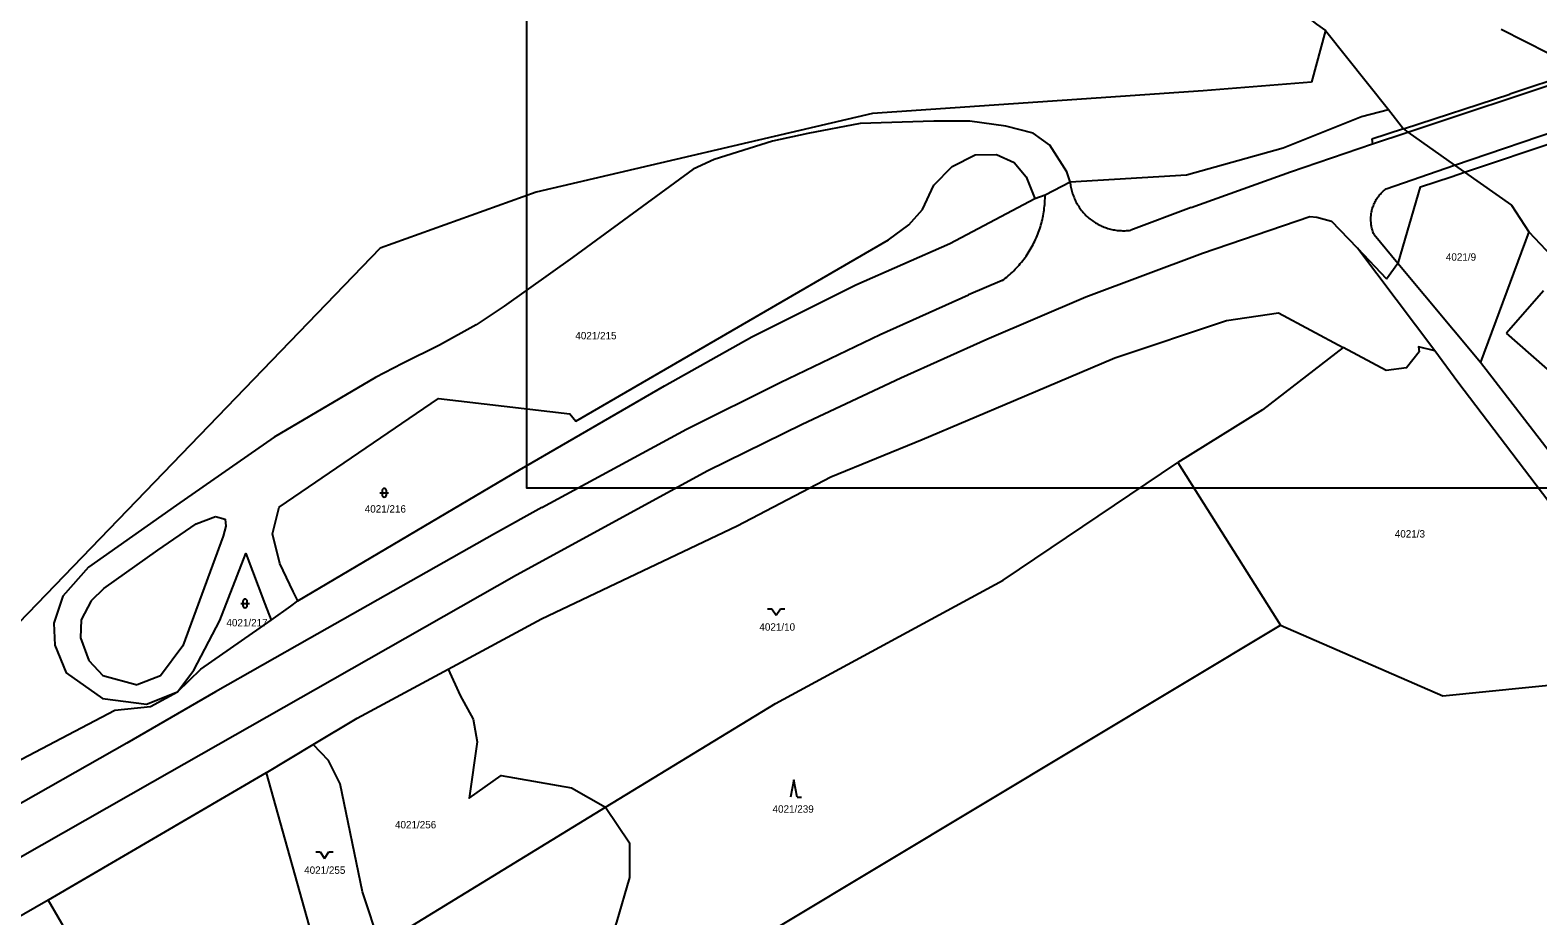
# Model space of a CAD drawing. Extents: x -869103 to -863415, y -1015889 to -1012477.
# Drawn here: x -867614.3 to -867267.3, y -1013598.4 to -1013394.6 of the extents above; entities that cross this region are included whole.
import ezdxf

# ---------------------------------------------------------------- set-up
doc = ezdxf.new("R2010")
doc.units = 0
for name, color, linetype in [('Hranice katastralního území', 7, 'Continuous'), ('Hranice parcel', 7, 'Continuous'), ('ML1000', 7, 'Continuous'), ('Parcelní čísla', 7, 'Continuous'), ('Vnitřní kresba', 7, 'Continuous'), ('Značky kultur', 7, 'Continuous')]:
    doc.layers.add(name, color=color, linetype=linetype)

msp = doc.modelspace()

# ---------------------------------------------------------------- linework, layer by layer
at = {"layer": 'Hranice katastralního území'}
msp.add_line((-867316.19, -1013394.74), (-867319.36, -1013406.56), dxfattribs=at)
for points in [[(-867342.67, -1013374.58), (-867330.42, -1013383.91), (-867327.52, -1013386.12), (-867321.46, -1013390.73), (-867318.19, -1013393.22), (-867316.19, -1013394.74)], [(-867319.36, -1013406.56), (-867344.3, -1013408.59), (-867420.44, -1013413.79), (-867497.84, -1013431.94), (-867533.79, -1013444.77), (-867635.74, -1013550.41), (-867753.76, -1013618.81)]]:
    msp.add_lwpolyline(points, dxfattribs=at)
at = {"layer": 'Hranice parcel'}
for p, q in [((-867316.19, -1013394.74), (-867319.36, -1013406.56)), ((-867316.19, -1013394.74), (-867301.67, -1013412.9)), ((-867257.25, -1013403.84), (-867275.71, -1013394.51)), ((-867307.87, -1013414.51), (-867301.67, -1013412.9)), ((-867269.34, -1013441), (-867280.47, -1013471.01)), ((-867302.08, -1013451.88), (-867299.47, -1013448.24)), ((-867299.47, -1013448.24), (-867299.32, -1013448.02)), ((-867299.47, -1013448.24), (-867280.47, -1013471.01)), ((-867326.96, -1013459.67), (-867312.12, -1013467.62)), ((-867285.68, -1013475.65), (-867290.97, -1013468.44)), ((-867250.1, -1013522.49), (-867285.68, -1013475.65)), ((-867350.14, -1013494.15), (-867326.55, -1013531.51)), ((-867326.55, -1013531.51), (-867289.11, -1013547.84)), ((-867560.01, -1013565.49), (-867549.22, -1013559.03)), ((-867560.01, -1013565.49), (-867610.16, -1013594.81)), ((-867560.01, -1013565.49), (-867546.67, -1013613.13)), ((-867489.72, -1013568.95), (-867481.86, -1013573.46)), ((-867533.74, -1013605.21), (-867481.86, -1013573.46)), ((-867481.86, -1013573.46), (-867476.41, -1013581.67)), ((-867533.74, -1013605.21), (-867537.85, -1013592.91)), ((-867610.16, -1013594.81), (-867618.83, -1013599.8)), ((-867610.16, -1013594.81), (-867585.92, -1013636.93))]:
    msp.add_line(p, q, dxfattribs=at)
for points in [[(-867342.67, -1013374.58), (-867330.42, -1013383.91), (-867327.52, -1013386.12), (-867321.46, -1013390.73), (-867318.19, -1013393.22), (-867316.19, -1013394.74)], [(-867319.36, -1013406.56), (-867344.3, -1013408.59), (-867420.44, -1013413.79), (-867497.84, -1013431.94), (-867533.79, -1013444.77), (-867635.74, -1013550.41), (-867753.76, -1013618.81)], [(-867301.67, -1013412.9), (-867298.21, -1013417.34), (-867297.17, -1013418.08), (-867286.44, -1013425.71), (-867284.15, -1013427.34)], [(-867374.93, -1013429.52), (-867375.68, -1013427.21), (-867379.62, -1013421.07), (-867383.48, -1013418.35), (-867389.72, -1013416.68), (-867398.04, -1013415.57), (-867406.32, -1013415.6), (-867423.28, -1013416.13), (-867435.3, -1013418.44), (-867443.46, -1013420.18), (-867456.89, -1013424.42), (-867461.74, -1013426.63), (-867489.48, -1013446.92), (-867505.2, -1013458.13), (-867511.7, -1013462.41), (-867520.1, -1013467.13), (-867528.6, -1013471.3), (-867534.88, -1013474.58), (-867558.14, -1013488.32), (-867580.62, -1013503.94), (-867600.88, -1013518.22), (-867606.83, -1013524.84), (-867608.91, -1013531.09), (-867608.65, -1013536.16), (-867606.03, -1013542.52), (-867597.67, -1013548.45), (-867587.53, -1013549.72), (-867580.45, -1013546.87)], [(-867374.93, -1013429.52), (-867348.14, -1013427.94), (-867325.89, -1013421.67), (-867307.87, -1013414.51)], [(-867552.75, -1013525.96), (-867553.8, -1013523.79), (-867556.9, -1013517.37), (-867558.56, -1013510.51), (-867557.02, -1013504.41), (-867520.32, -1013479.37), (-867490.1, -1013482.92), (-867488.74, -1013484.61), (-867416.74, -1013442.85), (-867412.04, -1013439.42), (-867408.89, -1013435.91), (-867406.29, -1013430.33), (-867402.13, -1013426.03), (-867396.77, -1013423.29), (-867391.86, -1013423.26), (-867387.8, -1013425.1), (-867385.03, -1013428.34), (-867383.05, -1013433.35)], [(-867299.32, -1013448.02), (-867294.3, -1013430.7), (-867287.22, -1013428.37), (-867284.15, -1013427.34)], [(-867284.15, -1013427.34), (-867273.32, -1013434.93), (-867269.34, -1013441)], [(-867383.05, -1013433.35), (-867380.7, -1013432.51), (-867374.93, -1013429.52)], [(-867552.75, -1013525.96), (-867501.66, -1013495.78), (-867468.31, -1013476.49), (-867448.21, -1013465.21), (-867424.27, -1013453.24), (-867402.6, -1013443.75), (-867383.05, -1013433.35)], [(-867269.34, -1013441), (-867241.95, -1013470), (-867213.99, -1013523.37)], [(-867290.97, -1013468.44), (-867308.82, -1013444.81), (-867302.08, -1013451.88)], [(-867518.15, -1013541.67), (-867496.64, -1013530.06), (-867451.58, -1013508.71), (-867430.05, -1013497.43), (-867409, -1013488.8), (-867388.01, -1013479.91), (-867364.62, -1013470.03), (-867338.93, -1013461.42), (-867326.96, -1013459.67)], [(-867312.12, -1013467.62), (-867330.63, -1013481.99), (-867350.14, -1013494.15)], [(-867294.58, -1013468.65), (-867297.48, -1013472.35), (-867302.16, -1013472.96), (-867312.12, -1013467.62)], [(-867290.97, -1013468.44), (-867294.74, -1013467.46), (-867294.58, -1013468.65)], [(-867280.47, -1013471.01), (-867241.81, -1013521.12), (-867224.29, -1013529.55), (-867213.99, -1013523.37)], [(-867481.86, -1013573.46), (-867442.79, -1013549.54), (-867390.35, -1013521.2), (-867350.14, -1013494.15)], [(-867580.45, -1013546.87), (-867576.67, -1013541.9), (-867570.67, -1013530.46), (-867564.73, -1013515.06), (-867560.29, -1013526.62), (-867558.85, -1013530.36)], [(-867558.85, -1013530.36), (-867554.31, -1013527.2), (-867552.75, -1013525.96)], [(-867580.45, -1013546.87), (-867575.05, -1013541.64), (-867558.85, -1013530.36)], [(-867488.53, -1013628.82), (-867464.48, -1013614.37), (-867326.55, -1013531.51)], [(-867289.11, -1013547.84), (-867248.82, -1013543.72), (-867230.89, -1013533.36)], [(-867549.22, -1013559.03), (-867539.05, -1013552.94), (-867518.15, -1013541.67)], [(-867518.15, -1013541.67), (-867515.32, -1013547.76), (-867512.35, -1013553.18), (-867511.46, -1013558.41), (-867513.3, -1013571.37), (-867505.89, -1013566.17), (-867489.72, -1013568.95)], [(-868123.92, -1013837.14), (-868079.76, -1013818.89), (-868033.21, -1013797.81), (-868012.01, -1013785.48), (-867950.07, -1013750.76), (-867862.98, -1013701.19), (-867776.75, -1013651.7), (-867688.32, -1013600.14), (-867594.86, -1013551.1), (-867586.66, -1013550.23), (-867580.45, -1013546.87)], [(-867537.85, -1013592.91), (-867542.99, -1013568.04), (-867545.69, -1013562.72), (-867549.22, -1013559.03)], [(-867476.41, -1013581.67), (-867476.41, -1013589.6), (-867479.36, -1013599.92), (-867488.53, -1013628.82)]]:
    msp.add_lwpolyline(points, dxfattribs=at)
at = {"layer": 'ML1000'}
msp.add_lwpolyline([(-867500, -1013000), (-866875, -1013000), (-866875, -1013500), (-867500, -1013500)], close=True, dxfattribs=at)
at = {"layer": 'Vnitřní kresba'}
for p, q in [((-867297.17, -1013418.08), (-867256.15, -1013404.4)), ((-867257.25, -1013403.84), (-867273.74, -1013409.37)), ((-867298.21, -1013417.34), (-867273.74, -1013409.37)), ((-867286.44, -1013425.71), (-867250.59, -1013413.43)), ((-867298.21, -1013417.34), (-867305.46, -1013419.71)), ((-867324.19, -1013427.23), (-867305.37, -1013420.81)), ((-867305.46, -1013419.71), (-867305.37, -1013420.81)), ((-867305.37, -1013420.81), (-867297.17, -1013418.08)), ((-867284.15, -1013427.34), (-867262.14, -1013419.95)), ((-867347.08, -1013435.42), (-867324.19, -1013427.23)), ((-867302.19, -1013431.11), (-867286.44, -1013425.71)), ((-867347.08, -1013435.42), (-867361, -1013440.66)), ((-867344.49, -1013445.94), (-867319.77, -1013437.5)), ((-867319.77, -1013437.5), (-867318.13, -1013437.66)), ((-867318.13, -1013437.66), (-867314.75, -1013438.6)), ((-867308.82, -1013444.81), (-867314.75, -1013438.6)), ((-867304.97, -1013441.65), (-867299.47, -1013448.24)), ((-867371.31, -1013455.97), (-867344.49, -1013445.94)), ((-867390.57, -1013452.27), (-867398.35, -1013455.55)), ((-867418.69, -1013464.63), (-867398.35, -1013455.55)), ((-867265.94, -1013454.62), (-867274.51, -1013464.37)), ((-867394.09, -1013465.77), (-867371.31, -1013455.97)), ((-867441.69, -1013475.72), (-867418.69, -1013464.63)), ((-867413.93, -1013474.66), (-867394.09, -1013465.77)), ((-867252.22, -1013483.99), (-867274.51, -1013464.37)), ((-867463.22, -1013486.46), (-867441.69, -1013475.72)), ((-867436.66, -1013485.3), (-867413.93, -1013474.66)), ((-867496.57, -1013504.45), (-867463.22, -1013486.46)), ((-867458.31, -1013495.92), (-867436.66, -1013485.3)), ((-867502.38, -1013519.99), (-867458.31, -1013495.92)), ((-867576.16, -1013508.25), (-867571.65, -1013506.55)), ((-867571.65, -1013506.55), (-867569.43, -1013507.12)), ((-867569.43, -1013507.12), (-867569.3, -1013508.79)), ((-867496.57, -1013504.45), (-867507.42, -1013510.56)), ((-867584.92, -1013514.29), (-867576.16, -1013508.25)), ((-867569.89, -1013511.06), (-867579.19, -1013536.34)), ((-867569.3, -1013508.79), (-867569.89, -1013511.06)), ((-867507.42, -1013510.56), (-867550.01, -1013534.61)), ((-867597.39, -1013523.11), (-867584.92, -1013514.29)), ((-867544.77, -1013544.07), (-867502.38, -1013519.99)), ((-867597.39, -1013523.11), (-867600.3, -1013525.94)), ((-867600.3, -1013525.94), (-867602.56, -1013530.31)), ((-867602.56, -1013530.31), (-867602.75, -1013534.49)), ((-867602.75, -1013534.49), (-867600.87, -1013539.7)), ((-867550.01, -1013534.61), (-867571.68, -1013546.91)), ((-867579.19, -1013536.34), (-867584.37, -1013543.17)), ((-867600.87, -1013539.7), (-867597.58, -1013543.16)), ((-867597.58, -1013543.16), (-867589.67, -1013545.25)), ((-867584.37, -1013543.17), (-867589.67, -1013545.25)), ((-867586.17, -1013567.6), (-867544.77, -1013544.07)), ((-867571.68, -1013546.91), (-867592.1, -1013558.73)), ((-867592.1, -1013558.73), (-867683.6, -1013610.49)), ((-867677.53, -1013619.45), (-867586.17, -1013567.6))]:
    msp.add_line(p, q, dxfattribs=at)
for points in [[(-867374.93, -1013429.52), (-867374.9, -1013429.83), (-867374.86, -1013430.14), (-867374.82, -1013430.45), (-867374.76, -1013430.76), (-867374.7, -1013431.06), (-867374.63, -1013431.36), (-867374.55, -1013431.67), (-867374.47, -1013431.97), (-867374.38, -1013432.26), (-867374.28, -1013432.56), (-867374.17, -1013432.85), (-867374.05, -1013433.14), (-867373.93, -1013433.43), (-867373.8, -1013433.71), (-867373.67, -1013433.99), (-867373.52, -1013434.27), (-867373.37, -1013434.54), (-867373.21, -1013434.81), (-867373.05, -1013435.08), (-867372.88, -1013435.34), (-867372.7, -1013435.59), (-867372.52, -1013435.85), (-867372.33, -1013436.09), (-867372.13, -1013436.34), (-867371.93, -1013436.57), (-867371.72, -1013436.81), (-867371.51, -1013437.03), (-867371.29, -1013437.25), (-867371.06, -1013437.47), (-867370.83, -1013437.68), (-867370.6, -1013437.88), (-867370.36, -1013438.08), (-867370.11, -1013438.27), (-867369.86, -1013438.46), (-867369.6, -1013438.64), (-867369.34, -1013438.81), (-867369.08, -1013438.97), (-867368.81, -1013439.13), (-867368.54, -1013439.29), (-867368.26, -1013439.43), (-867367.98, -1013439.57), (-867367.7, -1013439.7), (-867367.42, -1013439.82), (-867367.13, -1013439.94), (-867366.83, -1013440.05), (-867366.54, -1013440.15), (-867366.24, -1013440.24), (-867365.94, -1013440.33), (-867365.64, -1013440.41), (-867365.34, -1013440.48), (-867365.03, -1013440.55), (-867364.73, -1013440.6), (-867364.42, -1013440.65), (-867364.11, -1013440.69), (-867363.8, -1013440.72), (-867363.49, -1013440.75), (-867363.18, -1013440.76), (-867362.86, -1013440.77), (-867362.55, -1013440.77), (-867362.24, -1013440.77), (-867361.93, -1013440.75), (-867361.62, -1013440.73), (-867361.31, -1013440.7), (-867361, -1013440.66)], [(-867304.97, -1013441.65), (-867305.07, -1013441.41), (-867305.17, -1013441.17), (-867305.25, -1013440.92), (-867305.33, -1013440.67), (-867305.41, -1013440.42), (-867305.47, -1013440.17), (-867305.53, -1013439.91), (-867305.58, -1013439.65), (-867305.62, -1013439.4), (-867305.65, -1013439.14), (-867305.68, -1013438.88), (-867305.7, -1013438.61), (-867305.71, -1013438.35), (-867305.71, -1013438.09), (-867305.71, -1013437.83), (-867305.7, -1013437.57), (-867305.68, -1013437.31), (-867305.65, -1013437.05), (-867305.61, -1013436.79), (-867305.57, -1013436.53), (-867305.52, -1013436.28), (-867305.46, -1013436.02), (-867305.39, -1013435.77), (-867305.32, -1013435.52), (-867305.23, -1013435.27), (-867305.14, -1013435.02), (-867305.05, -1013434.78), (-867304.94, -1013434.54), (-867304.83, -1013434.3), (-867304.72, -1013434.07), (-867304.59, -1013433.84), (-867304.46, -1013433.61), (-867304.32, -1013433.39), (-867304.18, -1013433.17), (-867304.03, -1013432.96), (-867303.87, -1013432.75), (-867303.7, -1013432.55), (-867303.53, -1013432.35), (-867303.36, -1013432.16), (-867303.18, -1013431.97), (-867302.99, -1013431.78), (-867302.8, -1013431.61), (-867302.6, -1013431.44), (-867302.4, -1013431.27), (-867302.19, -1013431.11)], [(-867390.57, -1013452.27), (-867390.22, -1013452), (-867389.87, -1013451.73), (-867389.53, -1013451.45), (-867389.19, -1013451.17), (-867388.86, -1013450.88), (-867388.54, -1013450.58), (-867388.21, -1013450.28), (-867387.9, -1013449.97), (-867387.59, -1013449.66), (-867387.29, -1013449.34), (-867386.99, -1013449.01), (-867386.7, -1013448.68), (-867386.41, -1013448.35), (-867386.13, -1013448.01), (-867385.86, -1013447.66), (-867385.59, -1013447.31), (-867385.33, -1013446.96), (-867385.07, -1013446.6), (-867384.82, -1013446.23), (-867384.58, -1013445.87), (-867384.35, -1013445.49), (-867384.12, -1013445.12), (-867383.9, -1013444.73), (-867383.68, -1013444.35), (-867383.48, -1013443.96), (-867383.28, -1013443.57), (-867383.08, -1013443.17), (-867382.9, -1013442.77), (-867382.72, -1013442.37), (-867382.55, -1013441.96), (-867382.38, -1013441.56), (-867382.22, -1013441.14), (-867382.07, -1013440.73), (-867381.93, -1013440.31), (-867381.8, -1013439.89), (-867381.67, -1013439.47), (-867381.55, -1013439.05), (-867381.44, -1013438.62), (-867381.34, -1013438.19), (-867381.24, -1013437.76), (-867381.15, -1013437.33), (-867381.07, -1013436.9), (-867381, -1013436.46), (-867380.93, -1013436.03), (-867380.88, -1013435.59), (-867380.83, -1013435.15), (-867380.79, -1013434.71), (-867380.75, -1013434.27), (-867380.73, -1013433.83), (-867380.71, -1013433.39), (-867380.7, -1013432.95), (-867380.7, -1013432.51)]]:
    msp.add_lwpolyline(points, dxfattribs=at)
at = {"layer": 'Značky kultur'}
for p, q in [((-867533.33, -1013500.59), (-867533.33, -1013501.59)), ((-867532.33, -1013501.59), (-867532.33, -1013500.59)), ((-867533.83, -1013501.09), (-867531.83, -1013501.09)), ((-867565.87, -1013526.54), (-867563.87, -1013526.54)), ((-867565.37, -1013526.04), (-867565.37, -1013527.04)), ((-867564.37, -1013527.04), (-867564.37, -1013526.04)), ((-867444.63, -1013527.76), (-867443.63, -1013527.76)), ((-867443.63, -1013527.76), (-867442.63, -1013529.26)), ((-867442.63, -1013529.26), (-867441.63, -1013527.76)), ((-867441.63, -1013527.76), (-867440.63, -1013527.76)), ((-867438.56, -1013567.15), (-867439.31, -1013571.15)), ((-867437.81, -1013571.15), (-867438.56, -1013567.15)), ((-867437.81, -1013571.15), (-867436.81, -1013571.15)), ((-867548.57, -1013583.74), (-867547.57, -1013583.74)), ((-867547.57, -1013583.74), (-867546.57, -1013585.24)), ((-867546.57, -1013585.24), (-867545.57, -1013583.74)), ((-867545.57, -1013583.74), (-867544.57, -1013583.74))]:
    msp.add_line(p, q, dxfattribs=at)
for centre, start, end in [((-867532.83, -1013500.59), 0, 180), ((-867532.83, -1013501.59), 180, 359.9879), ((-867564.87, -1013526.04), 0, 180), ((-867564.87, -1013527.04), 180, 359.9879)]:
    msp.add_arc(centre, 0.5, start, end, dxfattribs=at)

# ---------------------------------------------------------------- texts
at = {"layer": 'Parcelní čísla'}
for s, p in [('4021/9', (-867288.44, -1013447.67)), ('4021/215', (-867488.84, -1013465.77)), ('4021/216', (-867537.32, -1013505.64)), ('4021/3', (-867300.2, -1013511.38)), ('4021/217', (-867569.16, -1013531.82)), ('4021/10', (-867446.47, -1013532.81)), ('4021/239', (-867443.44, -1013574.7)), ('4021/256', (-867530.35, -1013578.31)), ('4021/255', (-867551.26, -1013588.77))]:
    msp.add_text(s, height=1.7, dxfattribs=at).set_placement(p)

doc.saveas('drawing.dxf')
